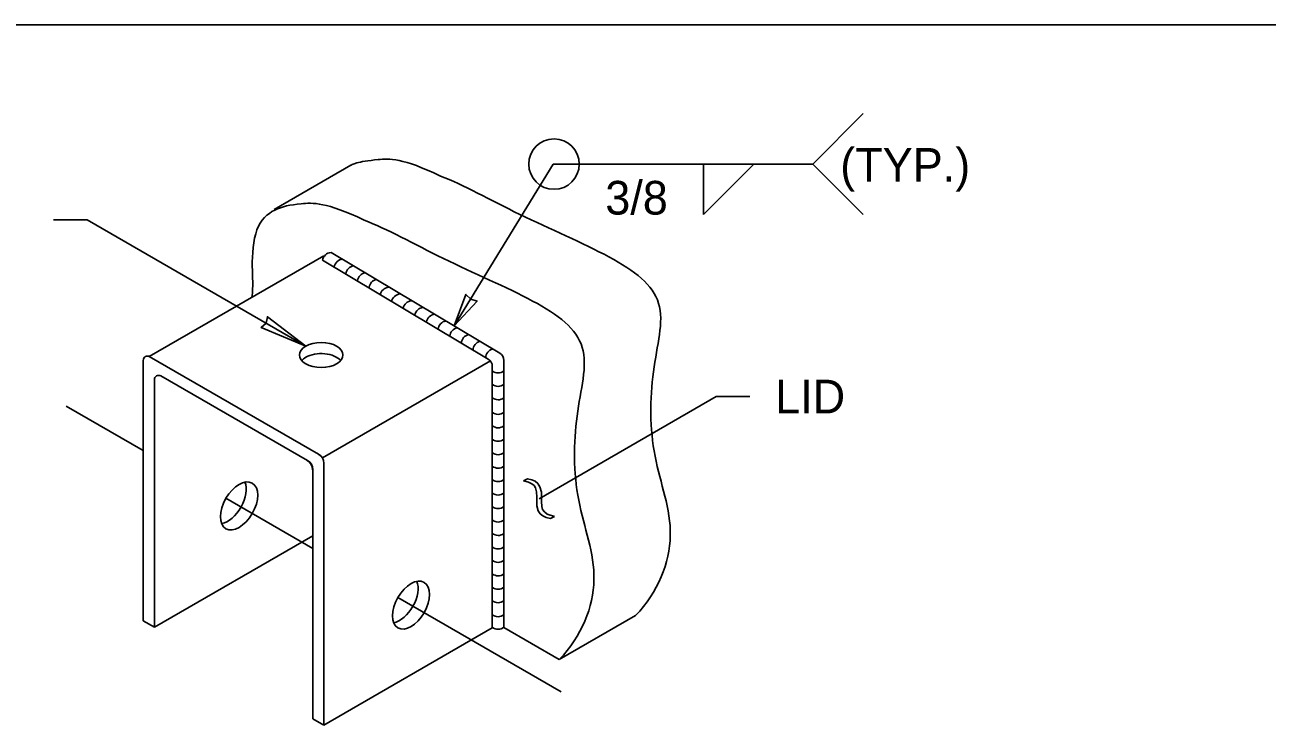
# Model space of a CAD drawing. Extents: x 99862 to 112891, y 95370 to 105076.
# Drawn here: x 101750 to 102341, y 104741 to 105076 of the extents above; entities that cross this region are included whole.
import ezdxf

# ---------------------------------------------------------------- set-up
doc = ezdxf.new("R2010")
doc.units = 0
for name, color, linetype in [('Level 1', 7, 'Continuous'), ('Level 15', 7, 'Continuous'), ('Level 20', 7, 'Continuous'), ('Level 7', 7, 'Continuous'), ('Level 8', 7, 'Continuous')]:
    doc.layers.add(name, color=color, linetype=linetype)

msp = doc.modelspace()

# ---------------------------------------------------------------- linework, layer by layer
at = {"layer": 'Level 1'}
for p, q in [((101868.86, 104987.75), (101905.17, 105008.72)), ((102004.36, 104773.63), (102040.67, 104794.59)), ((101977.97, 104788.86), (102004.36, 104773.63))]:
    msp.add_line(p, q, dxfattribs=at)
msp.add_lwpolyline([(99862, 102999.5), (103151, 102999.5), (103151, 105075.5), (99862, 105075.5)], close=True, dxfattribs=at)
for points in [[(101947.87, 105003.58), (101929.97, 105012.24), (101916.55, 105011.57), (101906.81, 105009.73), (101905.25, 105008.77), (101905.17, 105008.72)], [(101947.87, 105003.58), (101958.69, 104999.48), (101984.07, 104985.01), (102031.54, 104965.11), (102057.7, 104945.29), (102047.39, 104912), (102047.39, 104869.19), (102062.45, 104833.52), (102051.36, 104805.78), (102040.67, 104794.59)], [(101911.56, 104982.62), (101893.66, 104991.28), (101880.25, 104990.61), (101868.67, 104988.42), (101859.28, 104980.02), (101857.86, 104959.26), (101859, 104951.25), (101858.16, 104945.94)], [(101911.56, 104982.62), (101922.38, 104978.51), (101947.76, 104964.05), (101995.23, 104944.14), (102021.39, 104924.32), (102011.08, 104891.03), (102011.08, 104848.23), (102026.14, 104812.56), (102015.05, 104784.81), (102004.36, 104773.63)]]:
    msp.add_open_spline(points, degree=3, dxfattribs=at)
at = {"layer": 'Level 15'}
for p, q in [((102124.88, 105009.27), (102148.88, 105033.27)), ((101954.42, 104932.27), (102001.38, 105009.27)), ((102001.38, 105009.27), (102124.88, 105009.27)), ((102072.88, 105009.27), (102072.88, 104985.27)), ((102072.88, 104985.27), (102096.88, 105009.27)), ((102124.88, 105009.27), (102148.88, 104985.27)), ((101779.87, 104982.73), (101763.87, 104982.73)), ((101883.85, 104922.7), (101779.87, 104982.73)), ((101994.8, 104850.1), (102079.02, 104898.73)), ((102079.02, 104898.73), (102095.02, 104898.73)), ((101769.82, 104894.22), (101806.54, 104873.02)), ((101987.42, 104858.64), (101989.32, 104859.57)), ((101989.75, 104857.96), (101987.42, 104858.64)), ((101989.32, 104859.57), (101991.27, 104859.18)), ((101991.32, 104857.23), (101989.75, 104857.96)), ((101991.27, 104859.18), (101992.9, 104858.43)), ((101992.36, 104856.35), (101991.32, 104857.23)), ((101993.11, 104855.25), (101992.36, 104856.35)), ((101992.9, 104858.43), (101994.19, 104857.32)), ((101994.19, 104857.32), (101995.16, 104855.85)), ((101995.16, 104855.85), (101995.91, 104853.23)), ((101845.86, 104850.32), (101887.17, 104826.47)), ((101993.61, 104853.39), (101993.11, 104855.25)), ((101993.66, 104850.84), (101993.61, 104853.39)), ((101993.64, 104846.75), (101993.66, 104850.84)), ((101995.91, 104853.23), (101995.98, 104848.82)), ((101994.38, 104844.4), (101993.64, 104846.75)), ((101995.29, 104843), (101994.38, 104844.4)), ((101995.98, 104848.82), (101996.02, 104846.4)), ((101996.02, 104846.4), (101996.45, 104844.96)), ((101996.45, 104844.96), (101997.29, 104843.82)), ((101996.52, 104841.96), (101995.29, 104843)), ((101998.13, 104841.2), (101996.52, 104841.96)), ((101997.29, 104843.82), (101998.63, 104842.85)), ((102000.21, 104840.7), (101998.13, 104841.2)), ((101998.63, 104842.85), (102002.11, 104841.62)), ((102002.11, 104841.62), (102000.21, 104840.7)), ((101927.61, 104803.12), (102005.21, 104758.32))]:
    msp.add_line(p, q, dxfattribs=at)
for points in [[(101954.42, 104932.27), (101959.97, 104947.3), (101962.23, 104945.07), (101965.24, 104944.09)], [(101883.85, 104922.7), (101862.59, 104931.53), (101865, 104933.58), (101865.58, 104936.7)]]:
    msp.add_lwpolyline(points, close=True, dxfattribs=at)
msp.add_circle((102001.87, 105009.27), 12, dxfattribs=at)
at = {"layer": 'Level 7'}
for p, q in [((101892.38, 104965.72), (101809.4, 104917.81)), ((101806.54, 104915.94), (101806.54, 104792.03)), ((101809.4, 104917.81), (101889.87, 104871.35)), ((101891.7, 104869.52), (101971.59, 104915.65)), ((101811.85, 104906.76), (101811.85, 104788.97)), ((101814.95, 104908.6), (101884.67, 104868.35)), ((101887.17, 104864.02), (101887.17, 104745.48)), ((101892.37, 104867.02), (101892.37, 104742.47)), ((101887.17, 104832.46), (101811.85, 104788.97)), ((101806.54, 104792.03), (101811.85, 104788.97)), ((101972.51, 104788.74), (101892.37, 104742.47)), ((101887.17, 104745.48), (101892.38, 104742.48))]:
    msp.add_line(p, q, dxfattribs=at)
for centre, radius, start, end in [((101808.58, 104915.94), 2.04, 60, 180), ((101813.88, 104906.76), 2.04, 60, 180), ((101881.98, 104863.91), 5.1, 360, 60), ((101882.17, 104864.02), 5, 360, 60), ((101887.28, 104866.97), 5.1, 0, 60), ((101887.37, 104867.02), 5, 0, 60)]:
    msp.add_arc(centre, radius, start, end, dxfattribs=at)
for centre, major_axis in [((101891.16, 104918.48), (-10.34, 0)), ((101852.11, 104846.71), (-6.25, -10.83)), ((101933.86, 104799.52), (-6.25, -10.83))]:
    msp.add_ellipse(centre, major_axis=major_axis, ratio=0.57735, dxfattribs=at)
for centre, major_axis, start_param, end_param in [((101891.16, 104913.17), (-10.34, 0), 5.497787, 5.822943), ((101891.16, 104913.17), (-10.34, 0), 3.601835, 5.497787), ((101846.64, 104849.58), (-6.25, -10.83), 0.465715, 2.723468), ((101928.39, 104802.38), (-6.25, -10.83), 0.465715, 2.723468)]:
    msp.add_ellipse(centre, major_axis=major_axis, ratio=0.57735, start_param=start_param, end_param=end_param, dxfattribs=at)
at = {"layer": 'Level 8'}
for p, q in [((101891.81, 104963.53), (101970.56, 104916.54)), ((101895.83, 104967.23), (101976.02, 104919.38)), ((101977.97, 104788.86), (101977.97, 104915.94)), ((101972.51, 104913.1), (101972.51, 104788.74))]:
    msp.add_line(p, q, dxfattribs=at)
for points in [[(101891.81, 104963.53), (101970.56, 104916.54)], [(101976.02, 104919.38), (101895.83, 104967.23)], [(101977.97, 104788.97), (101977.97, 104915.94)], [(101972.51, 104913.1), (101972.51, 104789.01)]]:
    msp.add_lwpolyline(points, dxfattribs=at)
msp.add_lwpolyline([(101972.68, 104921.33), (101972.68, 104921.33), (101972.68, 104921.33), (101972.68, 104921.33)], close=True, dxfattribs=at)
msp.add_lwpolyline([(101972.68, 104921.33), (101972.68, 104921.33), (101972.68, 104921.33), (101972.68, 104921.33)], close=True, dxfattribs=at)
for centre, radius, start, end in [((101896.13, 104962.88), 4.37, 93.97385, 171.43522), ((101896.13, 104962.88), 4.37, 93.97385, 171.43522), ((101901.67, 104959.68), 4.37, 93.97385, 171.43522), ((101907.22, 104956.49), 4.37, 98.28405, 171.43522), ((101912.75, 104953.27), 4.37, 99.83767, 171.43522), ((101918.29, 104950.06), 4.37, 101.34372, 171.43522), ((101923.51, 104946.31), 4.37, 93.97385, 171.43522), ((101928.96, 104943.13), 4.37, 93.97385, 171.43522), ((101934.5, 104939.93), 4.37, 93.97385, 171.43522), ((101940.04, 104936.73), 4.37, 93.97385, 171.43522), ((101945.59, 104933.53), 4.37, 97.15981, 171.43522), ((101951.13, 104930.33), 4.37, 99.0822, 174.82603), ((101956.67, 104927.13), 4.37, 100.93036, 176.17418), ((101962.22, 104923.94), 4.37, 102.8124, 177.61582), ((101967.75, 104920.72), 4.37, 104.2376, 178.75499), ((101973.75, 104917.06), 4.37, 104.2376, 178.75499), ((101968.51, 104913.1), 4, 0, 59.1757), ((101968.51, 104913.1), 4, 0, 59.1757), ((101973.97, 104915.94), 4, 0, 59.1757), ((101973.97, 104915.94), 4, 0, 59.1757), ((101975.26, 104914.34), 4.37, 230.92636, 308.38773), ((101975.26, 104907.94), 4.37, 230.92636, 308.38773), ((101975.26, 104901.54), 4.37, 230.92636, 308.38773), ((101975.26, 104894.62), 4.37, 230.92636, 308.38773), ((101975.26, 104888.22), 4.37, 230.92636, 308.38773), ((101975.26, 104881.82), 4.37, 230.92636, 308.38773), ((101975.26, 104875.42), 4.37, 230.92636, 308.38773), ((101975.26, 104869.02), 4.37, 230.92636, 308.38773), ((101975.26, 104862.62), 4.37, 230.92636, 308.38773), ((101975.26, 104856.22), 4.37, 230.92636, 308.38773), ((101975.26, 104849.82), 4.37, 230.92636, 308.38773), ((101975.26, 104843.42), 4.37, 230.92636, 308.38773), ((101975.26, 104837.02), 4.37, 230.92636, 308.38773), ((101975.26, 104830.62), 4.37, 230.92636, 308.38773), ((101975.26, 104824.22), 4.37, 230.92636, 308.38773), ((101975.26, 104817.82), 4.37, 230.92636, 308.38773), ((101975.26, 104811.42), 4.37, 230.92636, 308.38773), ((101975.26, 104805.02), 4.37, 230.92636, 308.38773), ((101975.26, 104798.37), 4.37, 230.92636, 308.38773), ((101975.26, 104792.39), 4.37, 230.92636, 308.38773), ((101975.26, 104792.39), 4.37, 230.92636, 308.38773)]:
    msp.add_arc(centre, radius, start, end, dxfattribs=at)

# ---------------------------------------------------------------- texts
at = {"layer": 'Level 20'}
for s, p in [('(TYP.)', (102137.97, 105000.9)), ('3/8', (102026.24, 104985.27))]:
    msp.add_text(s, height=16, rotation=360, dxfattribs=at).set_placement(p)
msp.add_text('LID', height=16, dxfattribs=at).set_placement((102107.02, 104890.73))

doc.saveas('drawing.dxf')
